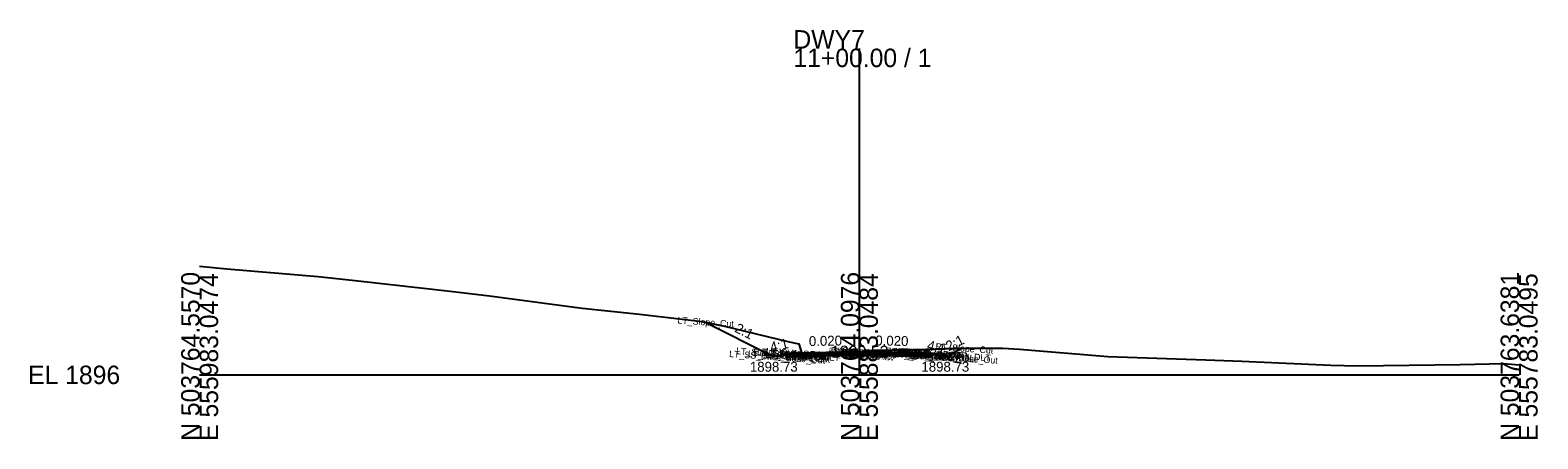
# Model space of a CAD drawing. Extents: x -26 to 1503, y -10 to 1052.
# Drawn here: x -25.7 to 202.8, y 990.3 to 1052.2 of the extents above; entities that cross this region are included whole.
import ezdxf

# ---------------------------------------------------------------- set-up
doc = ezdxf.new("R2010")
doc.units = 0
for name, color, linetype in [('Default', 7, 'Continuous'), ('Exist Cross Section Cell', 7, 'Continuous'), ('Exist XS Center Line Elevation Label', 7, 'Continuous'), ('Exist XS Ground Line', 7, 'Continuous'), ('Prop CMT Pvmt Course 1', 7, 'Continuous'), ('Prop CMT Pvmt Course 2', 7, 'Continuous'), ('Prop CMT Pvmt Surface', 7, 'Continuous'), ('Prop CMT Shld Paved Course 1', 7, 'Continuous'), ('Prop CMT Shld Paved Course 2', 7, 'Continuous'), ('Prop CMT Slope Grass', 7, 'Continuous'), ('Prop CMT Subgrade Earthwork', 7, 'Continuous'), ('Prop XS Ditch Standard Text', 7, 'Continuous'), ('Prop XS Earthwork Shape', 7, 'Continuous'), ('Prop XS SE Text', 7, 'Continuous'), ('Prop XS Side Slope Text', 7, 'Continuous'), ('Typical Text Asphalt at Bridge Approach CELL', 7, 'Continuous')]:
    doc.layers.add(name, color=color, linetype=linetype)

msp = doc.modelspace()

# ---------------------------------------------------------------- linework, layer by layer
at = {"layer": 'Exist Cross Section Cell'}
for p, q in [((100, 1000), (100, 1049.44)), ((0, 1000), (100, 1000)), ((100, 1000), (200, 1000))]:
    msp.add_line(p, q, dxfattribs=at)
at = {"layer": 'Exist XS Ground Line'}
for p, q in [((0, 1016.48), (4.11, 1016.07)), ((4.11, 1016.07), (17.98, 1014.92)), ((17.98, 1014.92), (24.02, 1014.25)), ((24.02, 1014.25), (37.98, 1012.71)), ((37.98, 1012.71), (43.93, 1011.97)), ((43.93, 1011.97), (57.98, 1010.11)), ((57.98, 1010.11), (66.66, 1009.19)), ((66.66, 1009.19), (75.79, 1008.15)), ((75.79, 1008.15), (79.53, 1007.39)), ((79.53, 1007.39), (89.35, 1005.03)), ((89.35, 1005.03), (90.82, 1004.71)), ((90.82, 1004.71), (91.33, 1003.08)), ((94.81, 1003.12), (100, 1003.52)), ((100, 1003.52), (101.9, 1003.67)), ((101.9, 1003.67), (108.16, 1003.81)), ((108.16, 1003.81), (110.07, 1003.83)), ((110.07, 1003.83), (112.96, 1003.93)), ((112.96, 1003.93), (116.42, 1004.06)), ((116.42, 1004.06), (121.74, 1004.03)), ((121.74, 1004.03), (124.25, 1003.89)), ((124.25, 1003.89), (137.66, 1002.78)), ((91.33, 1003.08), (93.13, 1003.05)), ((93.13, 1003.05), (93.6, 1003.01)), ((93.6, 1003.01), (94.81, 1003.12)), ((137.66, 1002.78), (152.53, 1002.28)), ((152.53, 1002.28), (157.98, 1002.06)), ((157.98, 1002.06), (171.44, 1001.49)), ((171.44, 1001.49), (175.57, 1001.36)), ((175.57, 1001.36), (191.08, 1001.59)), ((191.08, 1001.59), (197.7, 1001.71)), ((197.7, 1001.71), (200, 1001.51))]:
    msp.add_line(p, q, dxfattribs=at)
at = {"layer": 'Prop CMT Pvmt Course 1'}
for points in [[(100, 1003.51), (90, 1003.31)], [(90, 1003.31), (90, 1003.06)], [(90, 1003.06), (100, 1003.26)], [(100, 1003.26), (100, 1003.51)], [(100, 1003.51), (110, 1003.31)], [(100, 1003.26), (100, 1003.51)], [(110, 1003.06), (100, 1003.26)], [(110, 1003.31), (110, 1003.06)]]:
    msp.add_lwpolyline(points, dxfattribs=at)
msp.add_lwpolyline([(100, 1003.26), (100, 1003.39), (100, 1003.39), (100, 1003.26)], close=True, dxfattribs=at)
msp.add_lwpolyline([(100, 1003.26), (100, 1003.39), (100, 1003.39), (100, 1003.26)], close=True, dxfattribs=at)
at = {"layer": 'Prop CMT Pvmt Course 2'}
for points in [[(100, 1003.26), (90, 1003.06)], [(100, 1003.01), (100, 1003.26)], [(100, 1003.01), (100, 1003.26)], [(100, 1003.26), (110, 1003.06)], [(90, 1003.06), (90, 1002.81)], [(90, 1002.81), (100, 1003.01)], [(110, 1002.81), (100, 1003.01)], [(110, 1003.06), (110, 1002.81)]]:
    msp.add_lwpolyline(points, dxfattribs=at)
at = {"layer": 'Prop CMT Pvmt Surface'}
for points in [[(100, 1003.51), (90, 1003.31)], [(100, 1003.51), (110, 1003.31)]]:
    msp.add_lwpolyline(points, dxfattribs=at)
at = {"layer": 'Prop CMT Shld Paved Course 1'}
for points in [[(90, 1003.31), (89.74, 1003.06)], [(90, 1003.06), (90, 1003.31)], [(110, 1003.31), (110.26, 1003.06)], [(110, 1003.06), (110, 1003.31)], [(89.74, 1003.06), (90, 1003.06)], [(110.26, 1003.06), (110, 1003.06)]]:
    msp.add_lwpolyline(points, dxfattribs=at)
at = {"layer": 'Prop CMT Shld Paved Course 2'}
for points in [[(90, 1003.06), (89.74, 1003.06), (89.24, 1003.05), (89, 1002.8)], [(89, 1002.8), (90, 1002.81)], [(90, 1002.81), (90, 1003.06)], [(110, 1003.06), (110.26, 1003.06), (110.76, 1003.05), (111, 1002.8)], [(110, 1002.81), (110, 1003.06)], [(111, 1002.8), (110, 1002.81)]]:
    msp.add_lwpolyline(points, dxfattribs=at)
at = {"layer": 'Prop CMT Slope Grass'}
for points in [[(90, 1003.31), (89, 1003.23), (87, 1002.73), (76.43, 1008.02)], [(110, 1003.31), (111, 1003.23), (113, 1002.73), (115.59, 1004.03)]]:
    msp.add_lwpolyline(points, dxfattribs=at)
at = {"layer": 'Prop CMT Subgrade Earthwork'}
for points in [[(90, 1002.81), (89, 1002.8), (88.66, 1003.15)], [(100, 1003.01), (90, 1002.81)], [(100, 1003.01), (110, 1002.81)], [(110, 1002.81), (111, 1002.8), (111.34, 1003.15)]]:
    msp.add_lwpolyline(points, dxfattribs=at)
at = {"layer": 'Prop XS Earthwork Shape'}
for points in [[(76.43, 1008.02), (79.53, 1007.39), (89.35, 1005.03), (90.82, 1004.71), (91.25, 1003.34), (90, 1003.31), (89, 1003.23), (88.66, 1003.15), (87, 1002.73)], [(110, 1002.81), (111, 1002.8), (111.34, 1003.15), (111, 1003.23), (110, 1003.31), (100, 1003.51), (94.81, 1003.12), (93.6, 1003.01), (93.13, 1003.05), (91.33, 1003.08), (91.25, 1003.34), (90, 1003.31), (89, 1003.23), (88.66, 1003.15), (89, 1002.8), (90, 1002.81), (100, 1003.01)], [(111.34, 1003.15), (113, 1002.73), (115.59, 1004.03), (112.96, 1003.93), (110.07, 1003.83), (108.16, 1003.81), (101.9, 1003.67), (100, 1003.51), (110, 1003.31), (111, 1003.23)]]:
    msp.add_lwpolyline(points, close=True, dxfattribs=at)

# ---------------------------------------------------------------- texts
at = {"layer": 'Default'}
msp.add_text('-', height=0.0001, dxfattribs=at).set_placement((0, 1000))
at = {"layer": 'Exist Cross Section Cell'}
for s, p in [('DWY7', (90, 1049.44)), ('11+00.00 / 1', (90, 1046.64)), ('EL 1896', (-26, 998.6))]:
    msp.add_text(s, height=2.8, dxfattribs=at).set_placement(p)
for s, p in [('N 503764.5570', (0, 990)), ('E 555983.0474', (2.8, 990)), ('N 503764.0976', (100, 990)), ('E 555883.0484', (102.8, 990)), ('N 503763.6381', (200, 990)), ('E 555783.0495', (202.8, 990))]:
    msp.add_text(s, height=2.8, rotation=90, dxfattribs=at).set_placement(p)
at = {"layer": 'Exist XS Center Line Elevation Label'}
msp.add_text('1899.52', height=1.8, dxfattribs=at).set_placement((95.71, 1002.62))
at = {"layer": 'Prop XS Ditch Standard Text'}
for p in [(83.4, 1000.48), (109.4, 1000.48)]:
    msp.add_text('1898.73', height=1.5, dxfattribs=at).set_placement(p)
at = {"layer": 'Prop XS SE Text'}
for rotation, p in [(1.1458, (92.36, 1004.36)), (358.8542, (102.4, 1004.47))]:
    msp.add_text('0.020', height=1.5, rotation=rotation, dxfattribs=at).set_placement(p)
at = {"layer": 'Prop XS Side Slope Text'}
for s, rotation, p in [('2:1', 333.4349, (80.98, 1006.58)), ('2:1', 26.5651, (113.56, 1003.56)), ('4:1', 14.0362, (86.66, 1003.42)), ('4:1', 345.9638, (110.15, 1003.84))]:
    msp.add_text(s, height=1.5, rotation=rotation, dxfattribs=at).set_placement(p)
at = {"layer": 'Typical Text Asphalt at Bridge Approach CELL'}
for s, p in [('LT_Slope_Cut', (72.4, 1007.8)), ('LT_SS_Ditch_Base_Out', (80.24, 1002.71)), ('LT_Sub_Trench_Out_DLT', (81.29, 1003.16)), ('LT_Sub_Trench_Out', (83.09, 1002.72)), ('LT_PS2_Shelf_Out', (83.88, 1002.92)), ('LT_GS_OS_CTL', (84.44, 1003.05)), ('LT_PS2_OEOP', (85.51, 1002.85)), ('LT_PV2_OEOT', (85.72, 1002.86)), ('LT_Sub_OEOT', (85.74, 1002.61)), ('LT_PV1_OEOT', (85.84, 1003.1)), ('RT_PV2_OEEOP', (95.31, 1003.09)), ('RT_Sub_OEEOP', (95.33, 1002.84)), ('LT_PV2_OEEOP', (95.37, 1003.09)), ('LT_Sub_OEEOP', (95.39, 1002.84)), ('RT_PV1_OEEOP', (95.43, 1003.21)), ('LT_PV1_OEEOP', (95.49, 1003.2)), ('RT_PV2_IEEOP', (95.69, 1003.06)), ('LT_PV2_IEEOP', (95.75, 1003.06)), ('RT_PV1_IEEOP', (95.81, 1003.18)), ('LT_PV1_IEEOP', (95.87, 1003.18)), ('PV2_PGL', (97.32, 1002.95)), ('PV1_PGL', (97.44, 1003.19)), ('RT_Sub_Trench_Out_DLT', (103.92, 1003.17)), ('RT_Sub_Trench_Out', (105.03, 1002.72)), ('RT_PS2_Shelf_Out', (105.33, 1002.93)), ('RT_PV2_OEOT', (105.66, 1002.87)), ('RT_Sub_OEOT', (105.69, 1002.62)), ('RT_PV1_OEOT', (105.78, 1003.11)), ('RT_PS2_OEOP', (105.96, 1002.86)), ('RT_SS_Ditch_Base_Out', (106.18, 1002.71)), ('RT_GS_OS_CTL', (106.38, 1003.06)), ('RT_Slope_Cut', (111.51, 1003.81))]:
    msp.add_text(s, height=1, rotation=356, dxfattribs=at).set_placement(p)

doc.saveas('drawing.dxf')
